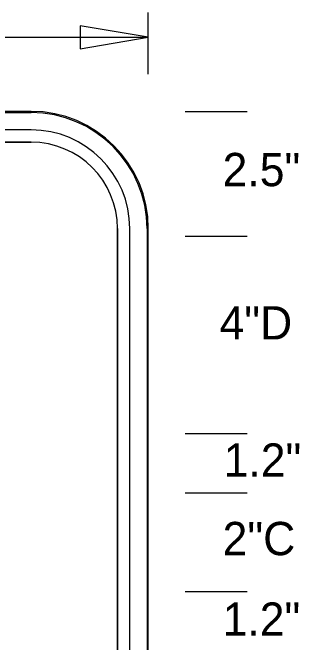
# Model space of a CAD drawing. Extents: x 0 to 770, y 0 to 495.
# Drawn here: x 135.4 to 165.6, y 406.9 to 473.2 of the extents above; entities that cross this region are included whole.
import ezdxf

# ---------------------------------------------------------------- set-up
doc = ezdxf.new("R2010")
doc.units = 0
for name, color, linetype in [('Dimension', 7, 'Continuous'), ('GSBWFill', 7, 'Continuous'), ('GSColorFill', 7, 'Continuous'), ('GSDims', 7, 'Continuous'), ('GSOutline', 7, 'Continuous'), ('TextStructures', 7, 'Continuous')]:
    doc.layers.add(name, color=color, linetype=linetype)

msp = doc.modelspace()

# ---------------------------------------------------------------- linework, layer by layer
at = {"layer": 'Dimension'}
msp.add_lwpolyline([(149.67, 470.567), (142.497, 471.782), (142.497, 469.351)], close=True, dxfattribs=at)
at = {"layer": 'GSBWFill'}
for p, q in [((137.34, 462.779), (99.701, 462.779)), ((137.34, 460.832), (99.701, 460.832)), ((99.701, 459.534), (137.34, 459.534)), ((146.425, 450.449), (146.425, 381.66)), ((147.723, 381.66), (147.723, 450.449)), ((149.67, 381.66), (149.67, 450.449))]:
    msp.add_line(p, q, dxfattribs=at)
for radius in [12.33, 10.383, 9.085]:
    msp.add_arc((137.34, 450.449), radius, 0, 90, dxfattribs=at)
at = {"layer": 'GSColorFill'}
for p, q in [((137.34, 462.779), (99.701, 462.779)), ((137.34, 462.779), (99.701, 462.779)), ((99.701, 462.649), (137.34, 462.649)), ((137.34, 460.832), (99.701, 460.832)), ((99.701, 459.534), (137.34, 459.534)), ((146.425, 450.449), (146.425, 381.66)), ((147.723, 381.66), (147.723, 450.449)), ((149.54, 450.449), (149.54, 381.66)), ((149.67, 381.66), (149.67, 450.449)), ((149.67, 381.66), (149.67, 450.449))]:
    msp.add_line(p, q, dxfattribs=at)
for radius in [12.33, 12.33, 12.2, 10.383, 9.085]:
    msp.add_arc((137.34, 450.449), radius, 0, 90, dxfattribs=at)
at = {"layer": 'GSDims'}
for p, q in [((149.67, 466.673), (149.67, 473.162)), ((87.371, 470.567), (149.67, 470.567)), ((153.564, 462.779), (160.053, 462.779)), ((153.564, 449.67), (160.053, 449.67)), ((153.564, 449.67), (160.053, 449.67)), ((153.564, 428.904), (160.053, 428.904)), ((153.564, 428.904), (160.053, 428.904)), ((153.564, 422.674), (160.053, 422.674)), ((153.564, 422.674), (160.053, 422.674)), ((153.564, 412.291), (160.053, 412.291)), ((153.564, 412.291), (160.053, 412.291))]:
    msp.add_line(p, q, dxfattribs=at)
at = {"layer": 'GSOutline'}
for p, q in [((137.34, 462.779), (99.701, 462.779)), ((137.34, 460.832), (99.701, 460.832)), ((137.34, 459.534), (99.701, 459.534)), ((146.425, 381.66), (146.425, 450.449)), ((147.723, 381.66), (147.723, 450.449)), ((149.67, 381.66), (149.67, 450.449))]:
    msp.add_line(p, q, dxfattribs=at)
for radius in [12.33, 10.383, 9.085]:
    msp.add_arc((137.34, 450.449), radius, 0, 90, dxfattribs=at)

# ---------------------------------------------------------------- texts
at = {"layer": 'TextStructures'}
for s, p in [('2.5"', (157.486, 454.91)), ('4"D', (157.158, 438.792)), ('1.2"', (157.595, 424.365)), ('2"C', (157.486, 416.113)), ('1.2"', (157.486, 407.643))]:
    msp.add_text(s, height=3.5, dxfattribs=at).set_placement(p)

doc.saveas('drawing.dxf')
